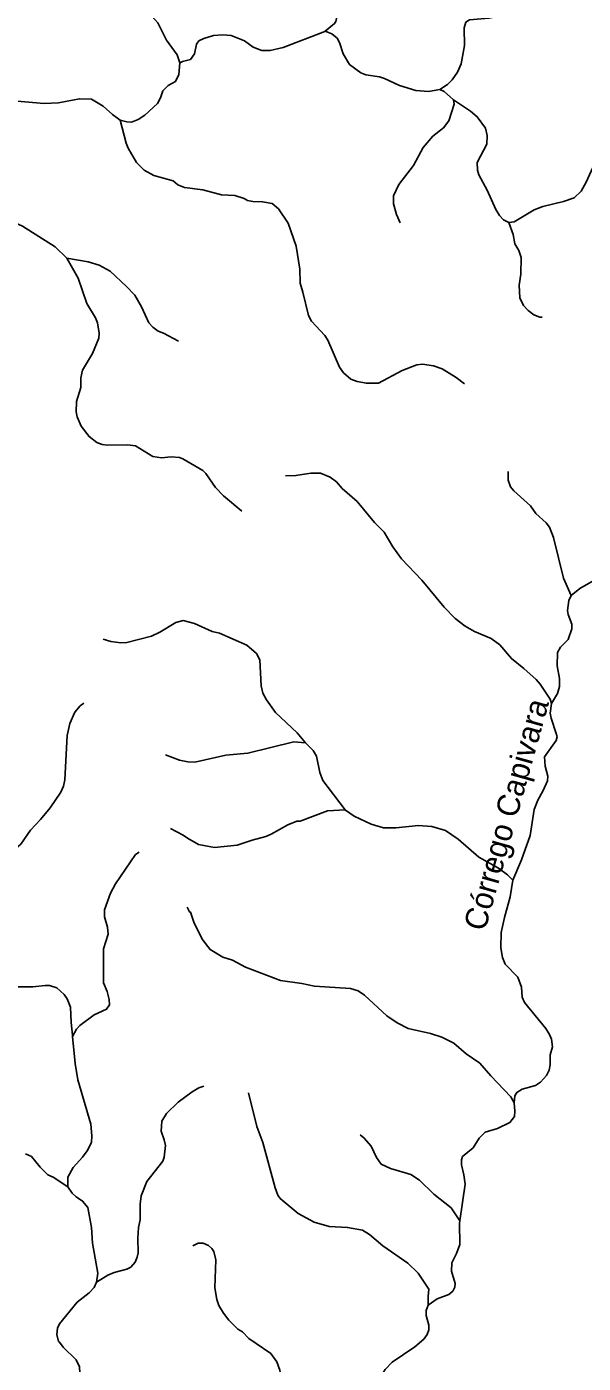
# Model space of a CAD drawing. Extents: x 500 to 555.2, y 9115.7 to 9171.
# Drawn here: x 528.19 to 532.13, y 9126.27 to 9135.74 of the extents above; entities that cross this region are included whole.
import ezdxf
from ezdxf.enums import TextEntityAlignment as Align

# ---------------------------------------------------------------- set-up
doc = ezdxf.new("R2010")
doc.units = 0
doc.header["$LTSCALE"] = 0.064
doc.layers.add('61', color=7, linetype='Continuous')
doc.layers.add('7', color=7, linetype='Continuous', lineweight=25)

msp = doc.modelspace()

# ---------------------------------------------------------------- linework, layer by layer
at = {"layer": '7'}
msp.add_line((528.854, 9135.0788), (528.8523, 9135.0792), dxfattribs=at)
for points in [[(528.1843, 9136.6492), (528.2214, 9136.6244), (528.2417, 9136.6028), (528.2863, 9136.4783), (528.32, 9136.4335), (528.3903, 9136.3647), (528.4351, 9136.3467), (528.4589, 9136.3281), (528.5174, 9136.2338), (528.5545, 9136.1964), (528.6161, 9136.1633), (528.7015, 9136.1447), (528.7584, 9136.1106), (528.7687, 9136.0904), (528.7751, 9136.0566), (528.7672, 9135.9682), (528.7719, 9135.9653), (528.7744, 9135.9385), (528.8036, 9135.9021), (529.0563, 9135.8397), (529.1201, 9135.7686), (529.1821, 9135.6478), (529.2558, 9135.5426), (529.2768, 9135.4849)], [(531.947, 9136.5478), (531.9359, 9136.4378), (531.9053, 9136.3412), (531.8204, 9136.223), (531.7797, 9136.1515), (531.7372, 9136.0394), (531.6828, 9135.9271), (531.6365, 9135.873), (531.5539, 9135.82), (531.4648, 9135.8019), (531.327, 9135.7898), (531.3024, 9135.7747), (531.29, 9135.7337), (531.2915, 9135.6084), (531.2695, 9135.4791), (531.2436, 9135.4208), (531.2048, 9135.3661), (531.1729, 9135.3324), (531.1171, 9135.2966)], [(530.4641, 9136.0116), (530.4626, 9136.0083), (530.4019, 9135.9185), (530.3878, 9135.8788), (530.3908, 9135.8216), (530.381, 9135.7779), (530.3724, 9135.764), (530.3046, 9135.7095)], [(530.3046, 9135.7095), (530.3029, 9135.7081), (530.0086, 9135.5957), (529.9147, 9135.5738), (529.8563, 9135.574), (529.796, 9135.5961), (529.7348, 9135.6426), (529.6391, 9135.6789), (529.5781, 9135.6837), (529.5133, 9135.679), (529.4463, 9135.6592), (529.4114, 9135.642), (529.3941, 9135.6187), (529.3803, 9135.5495), (529.3507, 9135.5097), (529.2955, 9135.4945), (529.2768, 9135.4849)], [(531.1171, 9135.2966), (531.0366, 9135.2836), (530.9473, 9135.2903), (530.8307, 9135.3246), (530.7257, 9135.3758), (530.6895, 9135.3869), (530.5926, 9135.4014), (530.5585, 9135.4156), (530.4772, 9135.4746), (530.432, 9135.549), (530.4072, 9135.6313), (530.3908, 9135.6607), (530.3524, 9135.6912), (530.3046, 9135.7095)], [(529.2768, 9135.4849), (529.2689, 9135.4038), (529.2459, 9135.3543), (529.1936, 9135.3245), (529.1543, 9135.2881), (529.1377, 9135.2377), (529.1171, 9135.1974), (529.0268, 9135.1154), (528.9803, 9135.0835), (528.9337, 9135.0655), (528.9009, 9135.0672), (528.854, 9135.0788)], [(528.8523, 9135.0792), (528.7982, 9135.1208), (528.7336, 9135.1789), (528.6502, 9135.2285), (528.5637, 9135.231), (528.4161, 9135.2033), (528.315, 9135.1984), (528.1231, 9135.2147), (528.0159, 9135.2015), (527.9202, 9135.1716), (527.8524, 9135.1281), (527.7872, 9135.0454)], [(530.8356, 9134.3533), (530.8097, 9134.4108), (530.7894, 9134.4876), (530.7893, 9134.5433), (530.8281, 9134.6236), (530.9306, 9134.7587), (530.9988, 9134.8872), (531.068, 9134.9665), (531.1434, 9135.0256), (531.1808, 9135.0758), (531.2189, 9135.1931), (531.2152, 9135.2244)], [(531.2152, 9135.2244), (531.1483, 9135.2823), (531.1171, 9135.2966)], [(531.6071, 9134.3552), (531.5676, 9134.3738), (531.54, 9134.405), (531.5149, 9134.4465), (531.4532, 9134.583), (531.3939, 9134.6925), (531.3834, 9134.7265), (531.3821, 9134.7804), (531.4505, 9134.9087), (531.4537, 9134.9712), (531.4401, 9135.0239), (531.3821, 9135.1042), (531.3357, 9135.1441), (531.2152, 9135.2244)], [(531.2927, 9133.2122), (531.2341, 9133.2561), (531.1335, 9133.3171), (531.0733, 9133.3398), (530.9946, 9133.3512), (530.9553, 9133.3463), (530.8504, 9133.307), (530.6829, 9133.2153), (530.597, 9133.2153), (530.5327, 9133.2281), (530.4868, 9133.2445), (530.4348, 9133.2895), (530.4058, 9133.3284), (530.3237, 9133.5219), (530.3024, 9133.5547), (530.2092, 9133.6555), (530.186, 9133.6958), (530.1482, 9133.8598), (530.1272, 9133.9248), (530.1252, 9134.0238), (530.099, 9134.1878), (530.0422, 9134.3504), (529.9758, 9134.4503), (529.9302, 9134.4883), (529.8622, 9134.5012), (529.7927, 9134.5036), (529.755, 9134.5109), (529.731, 9134.5243), (529.666, 9134.5453), (529.5708, 9134.5504), (529.4396, 9134.5864), (529.3091, 9134.6027), (529.2604, 9134.6221), (529.2273, 9134.6489), (529.092, 9134.6882), (529.0227, 9134.7243), (528.9685, 9134.7806), (528.9088, 9134.8819), (528.8949, 9134.9168), (528.854, 9135.0788)], [(532.5845, 9135.0403), (532.5287, 9134.9839), (532.4754, 9134.948), (532.3214, 9134.8873), (532.2626, 9134.8488), (532.2254, 9134.7975), (532.1546, 9134.6411), (532.119, 9134.5764), (532.0684, 9134.5305), (531.9946, 9134.5044), (531.8475, 9134.4683), (531.7863, 9134.4455), (531.6449, 9134.3601), (531.6071, 9134.3552)], [(528.4757, 9134.1014), (528.3931, 9134.1812), (528.1618, 9134.3288), (528.1138, 9134.3506), (528.0422, 9134.3962), (527.6648, 9134.7619), (527.6067, 9134.7985), (527.5618, 9134.8177)], [(531.8427, 9133.6832), (531.8251, 9133.6845), (531.7847, 9133.701), (531.7424, 9133.7319), (531.7096, 9133.7675), (531.6851, 9133.8217), (531.6803, 9133.9096), (531.6917, 9133.9884), (531.6933, 9134.1058), (531.6767, 9134.1555), (531.6493, 9134.203), (531.6374, 9134.2697), (531.6071, 9134.3552)], [(529.2655, 9133.5136), (529.16, 9133.5715), (529.1232, 9133.5844), (529.0844, 9133.6131), (529.0557, 9133.6438), (529.0052, 9133.7576), (528.9557, 9133.8401), (528.8988, 9133.902), (528.7819, 9134.0089), (528.7031, 9134.0533), (528.6254, 9134.0763), (528.4757, 9134.1014)], [(529.7137, 9132.3079), (529.5848, 9132.4172), (529.5286, 9132.4769), (529.4592, 9132.5771), (529.4384, 9132.5979), (529.298, 9132.6806), (529.2728, 9132.69), (529.2151, 9132.695), (529.1461, 9132.6871), (529.0836, 9132.6965), (528.961, 9132.7724), (528.9049, 9132.7788), (528.7605, 9132.7756), (528.7251, 9132.7804), (528.6886, 9132.7962), (528.6333, 9132.8374), (528.5759, 9132.9125), (528.549, 9132.9774), (528.5408, 9133.0141), (528.5424, 9133.086), (528.5747, 9133.1845), (528.5737, 9133.2535), (528.5865, 9133.308), (528.6569, 9133.4262), (528.7012, 9133.5344), (528.7046, 9133.5711), (528.6916, 9133.6432), (528.6787, 9133.6787), (528.6168, 9133.7796), (528.5564, 9133.9591), (528.4757, 9134.1014)], [(532.5705, 9132.8301), (532.5939, 9132.7813), (532.6068, 9132.7384), (532.6283, 9132.6033), (532.6283, 9132.4676), (532.6215, 9132.4427), (532.5463, 9132.2737), (532.4989, 9132.2129), (532.4721, 9132.1552), (532.4487, 9132.122), (532.3541, 9132.0237), (532.3295, 9131.9827), (532.28, 9131.8746), (532.2196, 9131.825), (532.1084, 9131.7621), (532.0474, 9131.7117)], [(530.0236, 9132.5593), (530.0983, 9132.5606), (530.2047, 9132.5788), (530.2723, 9132.5787), (530.3412, 9132.5494), (530.3849, 9132.5159), (530.4266, 9132.4695), (530.532, 9132.3769), (530.6546, 9132.2298), (530.7234, 9132.1609), (530.7847, 9132.0561), (530.8462, 9131.9711), (530.9909, 9131.8197), (531.1476, 9131.6287), (531.2253, 9131.5492), (531.2959, 9131.4933), (531.3627, 9131.4565), (531.4807, 9131.4071), (531.5424, 9131.3616), (531.625, 9131.2644), (531.7135, 9131.1939), (531.8005, 9131.1151), (531.8278, 9131.0827), (531.8984, 9130.9768), (531.9093, 9130.9458)], [(531.6026, 9132.5913), (531.6014, 9132.5291), (531.6181, 9132.482), (531.6428, 9132.452), (531.759, 9132.3457), (531.7984, 9132.2917), (531.8705, 9132.226), (531.8953, 9132.196), (531.9226, 9132.1224), (531.9928, 9131.835), (532.0474, 9131.7117)], [(532.0474, 9131.7117), (532.0326, 9131.6756), (532.0232, 9131.606), (532.026, 9131.576), (532.0524, 9131.5076), (532.0524, 9131.4742), (532.0257, 9131.4005), (531.9717, 9131.3446), (531.951, 9131.3065), (531.9492, 9131.213), (531.9657, 9131.1232), (531.9658, 9131.0662), (531.9523, 9131.0172), (531.9093, 9130.9458)], [(528.7317, 9131.4024), (528.7861, 9131.3854), (528.8584, 9131.3764), (528.9009, 9131.3786), (529.0748, 9131.4244), (529.1345, 9131.4519), (529.2468, 9131.521), (529.2986, 9131.5337), (529.3785, 9131.5121), (529.5041, 9131.4572), (529.5572, 9131.4438), (529.7497, 9131.3592), (529.818, 9131.3013), (529.8428, 9131.2556), (529.8514, 9131.0723), (529.8644, 9131.0194), (529.8888, 9130.9718), (529.9531, 9130.8826), (530.1068, 9130.7371), (530.1666, 9130.6677)], [(528.5954, 9130.9496), (528.5689, 9130.9285), (528.5322, 9130.8838), (528.4954, 9130.8043), (528.4785, 9130.7202), (528.4621, 9130.4061), (528.4521, 9130.3595), (528.4336, 9130.3187), (528.3573, 9130.2068), (528.2881, 9130.1233), (528.2167, 9130.0486), (528.1487, 9129.9494), (528.0988, 9129.9057), (528.0299, 9129.8681), (527.9924, 9129.8326), (527.9167, 9129.706), (527.7997, 9129.5816), (527.7563, 9129.4895), (527.7288, 9129.4475), (527.6408, 9129.3793), (527.6143, 9129.3521), (527.5926, 9129.3155), (527.5563, 9129.1659)], [(531.9093, 9130.9458), (531.9088, 9130.945), (531.9004, 9130.8774), (531.9052, 9130.841), (531.9424, 9130.7341), (531.9483, 9130.7087), (531.9426, 9130.6831), (531.8593, 9130.5676), (531.8639, 9130.5011), (531.882, 9130.4317), (531.8803, 9130.3987), (531.8506, 9130.3293), (531.8112, 9130.2604), (531.7851, 9130.1948), (531.7569, 9130.0107), (531.695, 9129.8379), (531.6346, 9129.6952)], [(529.1752, 9130.5825), (529.2744, 9130.5451), (529.3326, 9130.5331), (529.3817, 9130.5308), (529.6024, 9130.5806), (529.7584, 9130.5941), (530.0834, 9130.6742), (530.1666, 9130.6677)], [(530.1666, 9130.6677), (530.2205, 9130.6128), (530.2434, 9130.5719), (530.2667, 9130.4564), (530.2886, 9130.4001), (530.4466, 9130.1928)], [(529.2099, 9130.0604), (529.2998, 9130.0135), (529.3301, 9129.9907), (529.4074, 9129.9475), (529.5216, 9129.9252), (529.6824, 9129.9428), (529.7874, 9129.9788), (529.8839, 9130.0028), (529.9237, 9130.0193), (530.0416, 9130.0871), (530.1045, 9130.1114), (530.1283, 9130.1112), (530.3206, 9130.1866), (530.4466, 9130.1928)], [(530.4466, 9130.1928), (530.4487, 9130.1901), (530.5113, 9130.1466), (530.632, 9130.0916), (530.7191, 9130.0659), (530.807, 9130.0641), (530.9658, 9130.0805), (531.0602, 9130.0739), (531.158, 9130.0463), (531.2472, 9129.9838), (531.3943, 9129.8579), (531.5332, 9129.7783), (531.5966, 9129.7328), (531.6346, 9129.6952)], [(528.9865, 9129.8929), (528.9622, 9129.875), (528.8206, 9129.6691), (528.7835, 9129.6016), (528.7427, 9129.4841), (528.7409, 9129.4344), (528.7621, 9129.3619), (528.7668, 9129.3113), (528.7343, 9129.2079), (528.7343, 9128.9666), (528.7606, 9128.9055), (528.7751, 9128.8477), (528.7784, 9128.8107), (528.7571, 9128.78), (528.6695, 9128.7406), (528.5674, 9128.6651), (528.5442, 9128.6387), (528.5157, 9128.5865)], [(531.6346, 9129.6952), (531.6162, 9129.5754), (531.5751, 9129.4304), (531.5526, 9129.3243), (531.549, 9129.2152), (531.5621, 9129.1463), (531.5811, 9129.0997), (531.671, 9129.0068), (531.6964, 9128.9363), (531.6998, 9128.865), (531.7164, 9128.8275), (531.8689, 9128.6436), (531.8951, 9128.601), (531.9092, 9128.5664), (531.9164, 9128.5137), (531.9, 9128.456), (531.8999, 9128.3845), (531.8915, 9128.3479), (531.8728, 9128.311), (531.8311, 9128.2618), (531.7945, 9128.2384), (531.7, 9128.2121), (531.6636, 9128.1903), (531.6499, 9128.167), (531.6433, 9128.1158)], [(529.327, 9129.5026), (529.3437, 9129.4706), (529.351, 9129.468), (529.3746, 9129.397), (529.4334, 9129.277), (529.4897, 9129.2024), (529.5794, 9129.1494), (529.649, 9129.1261), (529.7415, 9129.0767), (529.9889, 9128.9836), (530.139, 9128.9616), (530.2296, 9128.9423), (530.4855, 9128.9258), (530.5387, 9128.9094), (530.5829, 9128.8798), (530.7432, 9128.7327), (530.8147, 9128.6828), (530.8936, 9128.6435), (531.0515, 9128.6081), (531.1324, 9128.5813), (531.2164, 9128.5399), (531.3052, 9128.4637), (531.4007, 9128.3967), (531.4778, 9128.308), (531.621, 9128.1597), (531.6433, 9128.1158)], [(527.5858, 9129.1349), (527.7299, 9129.0119), (527.8571, 9128.9427), (527.9181, 9128.9273), (527.9772, 9128.9209), (528.1169, 9128.9374), (528.2331, 9128.9374), (528.3209, 9128.9487), (528.3512, 9128.947), (528.4053, 9128.9316), (528.4571, 9128.8831), (528.4764, 9128.8526), (528.5015, 9128.7931), (528.5048, 9128.6857), (528.5148, 9128.5958), (528.5157, 9128.5865)], [(528.5157, 9128.5865), (528.5341, 9128.395), (528.5537, 9128.2802), (528.644, 9127.9646), (528.6523, 9127.8815), (528.649, 9127.8355), (528.619, 9127.777), (528.587, 9127.7306), (528.5211, 9127.6578), (528.4817, 9127.5902), (528.4825, 9127.5204)], [(529.4455, 9128.2344), (529.4099, 9128.2215), (529.3632, 9128.1936), (529.2647, 9128.1206), (529.1817, 9128.0396), (529.1486, 9127.9852), (529.1445, 9127.9144), (529.1657, 9127.8545), (529.1738, 9127.8132), (529.1656, 9127.7316), (529.1557, 9127.7038), (529.0424, 9127.558), (529.0019, 9127.4576), (528.9935, 9127.398), (528.9936, 9127.2878), (528.9821, 9127.233), (528.9771, 9127.1575), (528.9798, 9127.0535), (528.9736, 9127.0221), (528.9586, 9126.9865), (528.9281, 9126.9519), (528.8999, 9126.9378), (528.8103, 9126.9149), (528.7644, 9126.8954), (528.6852, 9126.8448)], [(529.7626, 9128.1878), (529.822, 9127.9477), (529.8625, 9127.8345), (529.9502, 9127.5138), (529.9695, 9127.4627), (529.9854, 9127.4384), (530.1139, 9127.3331), (530.2263, 9127.271), (530.3344, 9127.2392), (530.4645, 9127.2329), (530.5687, 9127.213), (530.6184, 9127.1841), (530.713, 9127.1031), (530.8907, 9126.9791), (530.965, 9126.9098), (531.0403, 9126.7968), (531.034, 9126.7449), (531.0354, 9126.6833)], [(531.6433, 9128.1158), (531.649, 9128.0571), (531.6456, 9128.0204), (531.6145, 9127.9777), (531.5266, 9127.9353), (531.4381, 9127.9095), (531.3966, 9127.8661), (531.3526, 9127.798), (531.2783, 9127.7358), (531.2702, 9127.7113), (531.2702, 9127.6766), (531.2882, 9127.607), (531.2964, 9127.5408), (531.2596, 9127.2811)], [(530.5523, 9127.8905), (530.5798, 9127.8687), (530.6305, 9127.8101), (530.6685, 9127.728), (530.7027, 9127.6811), (530.767, 9127.6517), (530.912, 9127.6088), (530.9733, 9127.5676), (531.0756, 9127.4701), (531.1974, 9127.3714), (531.2596, 9127.2811)], [(528.1816, 9127.7546), (528.2241, 9127.7364), (528.286, 9127.6598), (528.3399, 9127.6066), (528.3771, 9127.5885), (528.4825, 9127.5204)], [(528.4825, 9127.5204), (528.5124, 9127.4763), (528.5408, 9127.4496), (528.5866, 9127.4199), (528.623, 9127.3742), (528.6506, 9127.2324), (528.656, 9127.1218), (528.6947, 9126.9101), (528.6852, 9126.8448)], [(531.2596, 9127.2811), (531.2567, 9127.2603), (531.2604, 9127.1113), (531.2364, 9127.0478), (531.203, 9126.9827), (531.2014, 9126.924), (531.2273, 9126.836), (531.2231, 9126.8091), (531.2086, 9126.7826), (531.1825, 9126.7588), (531.098, 9126.727), (531.0354, 9126.6833)], [(529.3673, 9127.1028), (529.4063, 9127.1229), (529.4402, 9127.1229), (529.4792, 9127.1064), (529.5026, 9127.0847), (529.516, 9127.0636), (529.5298, 9127.004), (529.523, 9126.8054), (529.538, 9126.7218), (529.5514, 9126.6812), (529.5843, 9126.6248), (529.6227, 9126.5758), (529.687, 9126.5131), (529.7188, 9126.494), (529.7656, 9126.4471), (529.9201, 9126.339), (529.9628, 9126.2798), (529.9841, 9126.2226), (530.0006, 9126.1144), (530.0201, 9126.0623), (530.056, 9126.0162), (530.1293, 9125.9499), (530.1415, 9125.9017), (530.1322, 9125.8388)], [(528.6852, 9126.8448), (528.6686, 9126.8065), (528.633, 9126.7709), (528.5477, 9126.7037), (528.4229, 9126.5503), (528.4093, 9126.5199), (528.4031, 9126.4752), (528.416, 9126.4251), (528.4241, 9126.4208), (528.4489, 9126.385), (528.5422, 9126.2948), (528.5653, 9126.2461), (528.5682, 9126.1995), (528.5605, 9126.0782), (528.5687, 9126.0126), (528.5914, 9125.9477), (528.6392, 9125.8451), (528.653, 9125.7947)], [(531.0354, 9126.6833), (531.021, 9126.6457), (531.0209, 9126.6085), (531.0387, 9126.5414), (531.0389, 9126.5087), (531.0289, 9126.4753), (531.0047, 9126.4417), (530.9396, 9126.3864), (530.781, 9126.2793)], [(530.781, 9126.2793), (530.73, 9126.227), (530.7073, 9126.1892), (530.6694, 9126.0843), (530.6476, 9126.0468), (530.581, 9125.9858), (530.514, 9125.9389), (530.4795, 9125.9225), (530.2696, 9125.8667), (530.2019, 9125.8579), (530.1322, 9125.8388)]]:
    msp.add_lwpolyline(points, dxfattribs=at)

# ---------------------------------------------------------------- texts
at = {"layer": '61'}
msp.add_text('Córrego Capivara', height=0.16, rotation=74.358, dxfattribs=at).set_placement((531.6646, 9130.1388), align=Align.CENTER)

doc.saveas('drawing.dxf')
